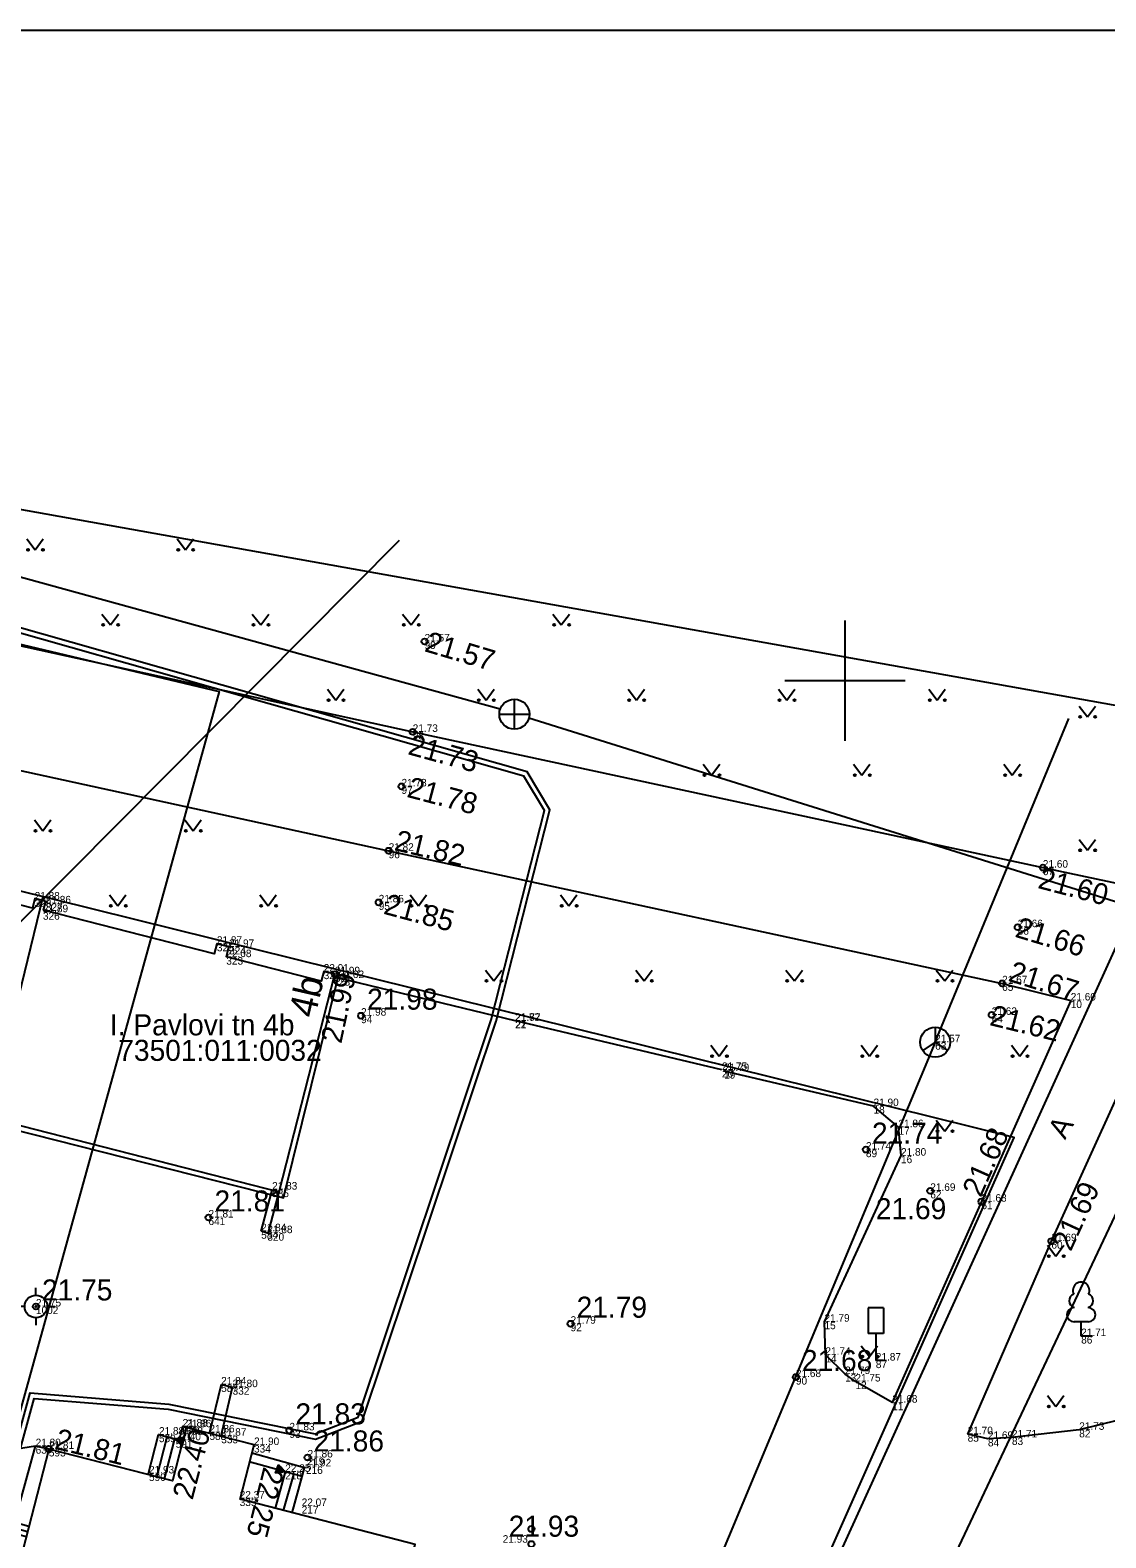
# Model space of a CAD drawing. Extents: x 714279 to 714471, y 6589851 to 6590083.
# Drawn here: x 714372.9 to 714408.7, y 6590021.5 to 6590071.6 of the extents above; entities that cross this region are included whole.
import ezdxf

# ---------------------------------------------------------------- set-up
doc = ezdxf.new("R2010")
doc.units = 0
for name, color, linetype in [('AED', 7, 'Continuous'), ('ALUSVORK', 7, 'Continuous'), ('HALJASTUS', 7, 'Continuous'), ('HOONE', 7, 'Continuous'), ('HOONEDET', 7, 'Continuous'), ('KKAEV', 7, 'Continuous'), ('KORGUS', 7, 'Continuous'), ('KTRASS', 7, 'Continuous'), ('LIIKLUS', 7, 'Continuous'), ('MOOTKORG', 7, 'Continuous'), ('MOOTMPUNKT', 7, 'Continuous'), ('MOOTPIIR', 7, 'Continuous'), ('MPKAABEL', 7, 'Continuous'), ('PIIR', 7, 'Continuous'), ('PUU', 7, 'Continuous'), ('SIKAEV', 7, 'Continuous'), ('SITRASS', 7, 'Continuous'), ('SKTRASS', 7, 'Continuous'), ('TEE', 7, 'Continuous'), ('VORK', 7, 'Continuous'), ('VORMISTUS', 7, 'Continuous'), ('VTRASS', 7, 'Continuous')]:
    doc.layers.add(name, color=color, linetype=linetype)

# ---------------------------------------------------------------- blocks, each defined once
blk = doc.blocks.new('RING02_1')
at = {"layer": 'KORGUS'}
blk.add_circle((0, 0), 0.2, dxfattribs=at)
blk = doc.blocks.new('RING02')
at = {"layer": 'KORGUS'}
blk.add_circle((0, 0), 0.2, dxfattribs=at)
blk = doc.blocks.new('SIKAEV')
at = {"layer": 'SIKAEV'}
for p, q in [((0, 0), (-0.83, -0.55)), ((0, 1), (0, 0)), ((0, 0), (0.83, -0.55))]:
    blk.add_line(p, q, dxfattribs=at)
blk.add_circle((0, 0), 1, dxfattribs=at)
blk = doc.blocks.new('RING02_2')
at = {"layer": 'KORGUS'}
blk.add_circle((0, 0), 0.2, dxfattribs=at)
blk = doc.blocks.new('LEHTP1')
at = {"layer": 'PUU'}
for p, q in [((0.48, 0.95), (-0.48, 0.95)), ((0, 0), (0, 0.95)), ((0.76, 0), (0, 0))]:
    blk.add_line(p, q, dxfattribs=at)
for centre, radius, start, end in [((0, 3.04), 0.554, 332.5799, 207.4201), ((-0.34, 2.35), 0.465, 109.0217, 253.1415), ((0.34, 2.35), 0.465, 286.8508, 70.9859), ((-0.47, 1.42), 0.475, 90.0016, 269.3953), ((0.47, 1.42), 0.475, 270.6047, 89.9984)]:
    blk.add_arc(centre, radius, start, end, dxfattribs=at)
blk = doc.blocks.new('LIIKLM')
at = {"layer": 'LIIKLUS'}
for p, q in [((-0.5, 3.5), (-0.5, 1.8)), ((0.5, 3.5), (-0.5, 3.5)), ((0.5, 3.5), (0.5, 1.8)), ((0.5, 1.8), (-0.5, 1.8)), ((0, 1.8), (0, 0)), ((0.5, 0), (0, 0))]:
    blk.add_line(p, q, dxfattribs=at)
blk = doc.blocks.new('RTKQRG')
at = {"layer": 'HOONEDET'}
for p, q in [((0, 0), (-0.49, 0.97)), ((0.49, 0.97), (-0.49, 0.97)), ((-0.48, 0.94), (0.21, 0.42)), ((-0.44, 0.97), (0.23, 0.46)), ((-0.42, 0.84), (0.19, 0.37)), ((-0.37, 0.74), (0.17, 0.33)), ((-0.35, 0.97), (0.26, 0.51)), ((-0.32, 0.63), (0.14, 0.28)), ((-0.27, 0.97), (0.28, 0.55)), ((-0.27, 0.53), (0.12, 0.24)), ((-0.22, 0.43), (0.1, 0.19)), ((-0.19, 0.97), (0.3, 0.6)), ((-0.17, 0.33), (0.07, 0.15)), ((-0.11, 0.97), (0.33, 0.64)), ((-0.11, 0.22), (0.05, 0.1)), ((-0.06, 0.12), (0.03, 0.05)), ((-0.02, 0.97), (0.35, 0.69)), ((-0.01, 0.02), (0, 0.01)), ((0, 0), (0.49, 0.97)), ((0.06, 0.97), (0.37, 0.73)), ((0.14, 0.97), (0.39, 0.78)), ((0.22, 0.97), (0.42, 0.83)), ((0.31, 0.97), (0.44, 0.87)), ((0.39, 0.97), (0.46, 0.92)), ((0.47, 0.97), (0.49, 0.96))]:
    blk.add_line(p, q, dxfattribs=at)
blk = doc.blocks.new('VQSA')
at = {"layer": 'HALJASTUS'}
for centre, radius in [((0, 2.3), 0.2), ((0, 1.3), 0.2), ((0, 0), 0.5), ((-2, -1.15), 0.2), ((-1.13, -0.65), 0.2), ((1.13, -0.65), 0.2), ((2, -1.15), 0.2)]:
    blk.add_circle(centre, radius, dxfattribs=at)
blk = doc.blocks.new('SPYMAR')
at = {"layer": 'ALUSVORK'}
for p, q in [((0, 0.75), (0, 1.25)), ((-0.75, 0), (-1.25, 0)), ((0.75, 0), (1.25, 0)), ((0, -0.75), (0, -1.25))]:
    blk.add_line(p, q, dxfattribs=at)
for radius in [0.75, 0.044]:
    blk.add_circle((0, 0), radius, dxfattribs=at)
blk = doc.blocks.new('KAKAEV')
at = {"layer": 'KKAEV'}
for p, q in [((-1, 0), (1, 0)), ((0, -1), (0, 1))]:
    blk.add_line(p, q, dxfattribs=at)
blk.add_circle((0, 0), 1, dxfattribs=at)
blk = doc.blocks.new('MURU_1')
at = {"layer": 'HALJASTUS'}
for p, q in [((-0.93, 1.21), (0, 0)), ((0, 0), (0.89, 1.21))]:
    blk.add_line(p, q, dxfattribs=at)
for centre in [(-0.8, 0), (0.86, 0)]:
    blk.add_circle(centre, 0.11, dxfattribs=at)

msp = doc.modelspace()

# ---------------------------------------------------------------- linework, layer by layer
at = {"layer": 'AED'}
for points in [[(714380.584, 6590031.676), (714380.945, 6590033.046)], [(714380.816, 6590031.599), (714381.181, 6590032.985)], [(714380.816, 6590031.599), (714380.584, 6590031.676)], [(714379.253, 6590026.577), (714378.863, 6590024.981), (714378.854, 6590024.945)], [(714379.249, 6590024.846), (714379.255, 6590024.871), (714379.255, 6590024.871), (714379.634, 6590026.487)], [(714379.253, 6590026.577), (714379.634, 6590026.487)], [(714381.948, 6590023.512), (714382.029, 6590023.801), (714380.27, 6590024.294)]]:
    msp.add_lwpolyline(points, dxfattribs=at)
at = {"layer": 'HOONE'}
for points in [[(714342.388, 6590042.923), (714381.181, 6590032.985), (714383.036, 6590040.226), (714382.666, 6590040.321), (714382.583, 6590039.999), (714379.427, 6590040.807), (714379.512, 6590041.139), (714379.11, 6590041.242), (714379.025, 6590040.91), (714373.344, 6590042.365), (714373.417, 6590042.65), (714373.056, 6590042.743), (714372.976, 6590042.431), (714367.537, 6590043.824)], [(714368.084, 6590003.497), (714362.833, 6589983.153), (714366.948, 6589982.091), (714366.479, 6589980.273), (714368.704, 6589979.699), (714369.168, 6589981.497), (714375.054, 6589979.978), (714385.707, 6590021.254), (714379.88, 6590022.758), (714380.346, 6590024.563), (714378.09, 6590025.145), (714377.63, 6590023.366), (714373.521, 6590024.426), (714369.05, 6590007.103), (714363.815, 6590008.455), (714364.534, 6590011.243), (714349.394, 6590015.151), (714346.235, 6590002.913), (714361.396, 6589999), (714362.901, 6590004.835), (714368.084, 6590003.497)], [(714378.09, 6590025.145), (714377.969, 6590025.177), (714377.855, 6590024.734)], [(714376.828, 6590023.573), (714377.174, 6590024.91), (714377.976, 6590024.703)], [(714377.116, 6590023.498), (714377.461, 6590024.836)], [(714377.372, 6590023.432), (714377.717, 6590024.769)], [(714381.61, 6590022.307), (714381.948, 6590023.512), (714380.189, 6590024.005)], [(714381.385, 6590023.67), (714381.047, 6590022.464)], [(714381.659, 6590023.586), (714381.321, 6590022.38)]]:
    msp.add_lwpolyline(points, dxfattribs=at)
at = {"layer": 'KORGUS'}
for centre in [(714383.036, 6590040.226), (714378.832, 6590032.133), (714373.093, 6590029.172), (714373.523, 6590024.432)]:
    msp.add_circle(centre, 0.1, dxfattribs=at)
at = {"layer": 'KTRASS'}
for points in [[(714388.535, 6590049.05), (714348.653, 6590060.023)], [(714409.141, 6590042.598), (714389.491, 6590048.747)], [(714399.928, 6590021.168), (714409.418, 6590042.018)]]:
    msp.add_lwpolyline(points, dxfattribs=at)
at = {"layer": 'MOOTPIIR'}
msp.add_lwpolyline([(714325.392, 6590064.148), (714418.405, 6590047.495), (714428.059, 6590039.059), (714392.952, 6589961.13), (714372.822, 6589966.903), (714302.696, 6589965.199), (714319.941, 6590042.637), (714325.392, 6590064.148)], dxfattribs=at)
at = {"layer": 'MPKAABEL'}
for points in [[(714372.812, 6590021.678), (714371.882, 6590021.934), (714373.032, 6590026.115), (714377.491, 6590025.755), (714382.392, 6590024.752), (714383.947, 6590025.358), (714388.404, 6590038.665), (714390.19, 6590045.703), (714389.431, 6590046.965), (714361.096, 6590055.017), (714347.738, 6590058.234), (714329.065, 6590059.739), (714322.338, 6590060.654), (714317.026, 6590061.747)], [(714372.768, 6590021.51), (714371.67, 6590021.813), (714372.903, 6590026.299), (714377.515, 6590025.926), (714382.377, 6590024.932), (714383.808, 6590025.49), (714388.238, 6590038.714), (714390.005, 6590045.675), (714389.318, 6590046.817), (714361.052, 6590054.85), (714347.71, 6590058.063), (714329.047, 6590059.566), (714322.309, 6590060.484), (714316.991, 6590061.578)]]:
    msp.add_lwpolyline(points, dxfattribs=at)
at = {"layer": 'PIIR'}
for points in [[(714313.433, 6589985.9), (714378.228, 6589973.152), (714405.629, 6590034.791), (714332.408, 6590052.951), (714332.595, 6590052.951)], [(714373.326, 6590042.802), (714371.485, 6590035.288), (714381.325, 6590032.79), (714383.187, 6590040.304)]]:
    msp.add_lwpolyline(points, dxfattribs=at)
at = {"layer": 'SITRASS'}
for points in [[(714320.359, 6590061.207), (714337.402, 6590059.587), (714379.185, 6590049.636), (714371.595, 6590022.212), (714372.86, 6590021.865)], [(714403.003, 6590037.966), (714407.447, 6590048.741)], [(714403.003, 6590037.966), (714373.288, 6589966.766)]]:
    msp.add_lwpolyline(points, dxfattribs=at)
at = {"layer": 'SKTRASS'}
msp.add_lwpolyline([(714355.498, 6590024.768), (714385.19, 6590054.667)], dxfattribs=at)
at = {"layer": 'TEE'}
for points in [[(714333.617, 6590059.437), (714358.94, 6590054.148), (714385.625, 6590048.292), (714406.584, 6590043.775), (714409.241, 6590043.211)], [(714332.593, 6590055.546), (714358.028, 6590050.175), (714384.824, 6590044.337), (714405.232, 6590039.925)], [(714389.03, 6590038.681), (714383.172, 6590040.1)], [(714405.232, 6590039.925), (714405.232, 6590039.925), (714407.513, 6590039.354)], [(714407.513, 6590039.354), (714401.577, 6590025.972), (714400.35, 6590026.676), (714400.006, 6590026.924), (714399.352, 6590027.564), (714399.321, 6590028.666), (714401.867, 6590034.191), (714401.782, 6590035.138), (714400.953, 6590035.84), (714395.983, 6590037.004)], [(714395.911, 6590037.044), (714389.038, 6590038.673)], [(714404.084, 6590024.922), (714404.084, 6590024.922), (714406.869, 6590031.347), (714410.261, 6590038.815), (714411.152, 6590038.233), (714411.748, 6590037.728), (714412.277, 6590037.152), (714412.789, 6590036.481), (714413.097, 6590035.78), (714413.331, 6590034.96), (714413.433, 6590034.186), (714413.432, 6590033.354), (714413.365, 6590032.606), (714413.139, 6590031.771), (714412.887, 6590030.992), (714410.681, 6590026.115), (714409.734, 6590025.55), (714407.795, 6590025.068), (714405.557, 6590024.814), (714404.758, 6590024.766), (714404.084, 6590024.922)], [(714368.928, 6590009.453), (714373.082, 6590024.523), (714370.895, 6590024.179), (714369.109, 6590016.749), (714367.271, 6590009.843)], [(714373.521, 6590024.426), (714373.082, 6590024.523)]]:
    msp.add_lwpolyline(points, dxfattribs=at)
at = {"layer": 'VORK'}
for p, q in [((714400, 6590052), (714400, 6590048)), ((714398, 6590050), (714402, 6590050))]:
    msp.add_line(p, q, dxfattribs=at)
at = {"layer": 'VORMISTUS'}
msp.add_lwpolyline([(714471.122, 6589929.143), (714278.622, 6589929.143), (714278.622, 6590071.643), (714471.122, 6590071.643), (714471.122, 6589929.143)], dxfattribs=at)
at = {"layer": 'VTRASS'}
msp.add_lwpolyline([(714378.183, 6589965.384), (714401.816, 6590016.993), (714414.734, 6590044.36), (714416.367, 6590047.881)], dxfattribs=at)

# ---------------------------------------------------------------- block references
at = {"layer": 'ALUSVORK', "xscale": 0.5, "yscale": 0.5}
msp.add_blockref('SPYMAR', (714373.093, 6590029.172), dxfattribs=at)
at = {"layer": 'HALJASTUS'}
for name, p, xscale, yscale in [('MURU_1', (714373.068, 6590054.352), 0.3, 0.3), ('MURU_1', (714378.068, 6590054.352), 0.3, 0.3), ('MURU_1', (714375.568, 6590051.852), 0.3, 0.3), ('MURU_1', (714380.568, 6590051.852), 0.3, 0.3), ('MURU_1', (714385.568, 6590051.852), 0.3, 0.3), ('MURU_1', (714390.568, 6590051.852), 0.3, 0.3), ('MURU_1', (714383.068, 6590049.352), 0.3, 0.3), ('MURU_1', (714388.068, 6590049.352), 0.3, 0.3), ('MURU_1', (714393.068, 6590049.352), 0.3, 0.3), ('MURU_1', (714398.068, 6590049.352), 0.3, 0.3), ('MURU_1', (714403.068, 6590049.352), 0.3, 0.3), ('MURU_1', (714408.068, 6590048.789), 0.3, 0.3), ('MURU_1', (714395.568, 6590046.852), 0.3, 0.3), ('MURU_1', (714400.568, 6590046.852), 0.3, 0.3), ('MURU_1', (714405.568, 6590046.852), 0.3, 0.3), ('MURU_1', (714373.32, 6590045.004), 0.3, 0.3), ('MURU_1', (714378.32, 6590045.004), 0.3, 0.3), ('MURU_1', (714408.068, 6590044.352), 0.3, 0.3), ('MURU_1', (714375.82, 6590042.504), 0.3, 0.3), ('MURU_1', (714380.82, 6590042.504), 0.3, 0.3), ('MURU_1', (714385.82, 6590042.504), 0.3, 0.3), ('MURU_1', (714390.82, 6590042.504), 0.3, 0.3), ('MURU_1', (714388.32, 6590040.004), 0.3, 0.3), ('MURU_1', (714393.32, 6590040.004), 0.3, 0.3), ('MURU_1', (714398.32, 6590040.004), 0.3, 0.3), ('MURU_1', (714403.32, 6590040.004), 0.3, 0.3), ('MURU_1', (714395.82, 6590037.504), 0.3, 0.3), ('MURU_1', (714400.82, 6590037.504), 0.3, 0.3), ('MURU_1', (714405.82, 6590037.504), 0.3, 0.3), ('MURU_1', (714403.32, 6590035.004), 0.3, 0.3), ('MURU_1', (714407.02, 6590030.846), 0.3, 0.3), ('MURU_1', (714400.82, 6590027.504), 0.3, 0.3), ('MURU_1', (714407.02, 6590025.846), 0.3, 0.3), ('VQSA', (714389.571, 6590020.618), 0.5, 0.5)]:
    msp.add_blockref(name, p, dxfattribs=dict(at, xscale=xscale, yscale=yscale))
at = {"layer": 'HOONEDET'}
for p, xscale, yscale, rotation in [((714377.717, 6590024.769), 0.29999999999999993, 0.3, -106.23872594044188), ((714381.385, 6590023.67), 0.3, -0.3, -109.050816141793)]:
    msp.add_blockref('RTKQRG', p, dxfattribs=dict(at, xscale=xscale, yscale=yscale, rotation=rotation))
at = {"layer": 'KKAEV', "xscale": 0.5, "yscale": 0.5}
msp.add_blockref('KAKAEV', (714389.006, 6590048.881), dxfattribs=at)
at = {"layer": 'KORGUS', "xscale": 0.5, "yscale": 0.5}
for name, p in [('RING02', (714386.02, 6590051.301)), ('RING02_2', (714385.625, 6590048.292)), ('RING02_1', (714385.251, 6590046.478)), ('RING02_2', (714384.824, 6590044.337)), ('RING02_2', (714406.584, 6590043.775)), ('RING02', (714384.494, 6590042.619)), ('RING02_1', (714405.748, 6590041.793)), ('RING02_2', (714405.232, 6590039.925)), ('RING02', (714383.908, 6590038.849)), ('RING02', (714404.885, 6590038.876)), ('RING02', (714400.7, 6590034.391)), ('RING02', (714402.841, 6590033.02)), ('RING02_1', (714404.542, 6590032.66)), ('RING02_1', (714406.869, 6590031.347)), ('RING02', (714390.876, 6590028.598)), ('RING02', (714398.371, 6590026.823)), ('RING02', (714381.523, 6590025.049)), ('RING02_1', (714382.128, 6590024.147))]:
    msp.add_blockref(name, p, dxfattribs=at)
at = {"layer": 'LIIKLUS', "xscale": 0.5, "yscale": 0.5}
msp.add_blockref('LIIKLM', (714401.029, 6590027.372), dxfattribs=at)
at = {"layer": 'PUU', "xscale": 0.5, "yscale": 0.5}
msp.add_blockref('LEHTP1', (714407.859, 6590028.187), dxfattribs=at)
at = {"layer": 'SIKAEV', "xscale": 0.5, "yscale": 0.5}
msp.add_blockref('SIKAEV', (714403.003, 6590037.966), dxfattribs=at)

# ---------------------------------------------------------------- texts
at = {"layer": 'HOONE'}
msp.add_text('4b', height=0.9, rotation=77.1111, dxfattribs=at).set_placement((714382.373, 6590038.744))
at = {"layer": 'HOONEDET'}
for s, rotation, p in [('22.40', 75.1609, (714378.3, 6590022.711)), ('22.25', 255.7051, (714380.668, 6590023.863))]:
    msp.add_text(s, height=0.7, rotation=rotation, dxfattribs=at).set_placement(p)
at = {"layer": 'KORGUS'}
for s, rotation, p in [('21.57', 343.3438, (714385.985, 6590050.982)), ('21.73', 344.5987, (714385.433, 6590047.554)), ('21.78', 345.1188, (714385.4, 6590046.134)), ('21.82', 346.6705, (714384.983, 6590044.361)), ('21.60', 345.2509, (714406.386, 6590043.102)), ('21.85', 344.948, (714384.623, 6590042.245)), ('21.66', 343.0663, (714405.625, 6590041.48)), ('21.67', 342.5464, (714405.401, 6590040.014)), ('21.99', 77.9478, (714383.248, 6590037.896)), ('21.62', 346.1662, (714404.785, 6590038.541)), ('21.68', 66.1218, (714404.52, 6590032.776)), ('21.69', 65.2812, (714407.514, 6590030.978)), ('21.81', 346.1293, (714373.683, 6590024.445))]:
    msp.add_text(s, height=0.7, rotation=rotation, dxfattribs=at).set_placement(p)
for s, p in [('21.98', (714384.108, 6590039.049)), ('21.74', (714400.9, 6590034.591)), ('21.81', (714379.032, 6590032.333)), ('21.69', (714401.031, 6590032.077)), ('21.75', (714373.293, 6590029.372)), ('21.79', (714391.076, 6590028.798)), ('21.68', (714398.571, 6590027.023)), ('21.83', (714381.723, 6590025.249)), ('21.86', (714382.328, 6590024.347)), ('21.93', (714388.818, 6590021.511))]:
    msp.add_text(s, height=0.7, dxfattribs=at).set_placement(p)
at = {"layer": 'MOOTKORG'}
for s, p in [('21.57', (714386.02, 6590051.301)), ('21.73', (714385.625, 6590048.292)), ('21.78', (714385.251, 6590046.478)), ('21.82', (714384.824, 6590044.337)), ('21.60', (714406.584, 6590043.775)), ('21.88', (714373.049, 6590042.714)), ('21.89', (714373.325, 6590042.291)), ('21.86', (714373.42, 6590042.586)), ('21.85', (714384.494, 6590042.619)), ('21.66', (714405.748, 6590041.793)), ('21.87', (714379.111, 6590041.241)), ('22.08', (714379.424, 6590040.797)), ('21.97', (714379.516, 6590041.137)), ('22.01', (714382.664, 6590040.315)), ('21.99', (714383.036, 6590040.226)), ('22.02', (714383.172, 6590040.1)), ('21.67', (714405.232, 6590039.925)), ('21.60', (714407.513, 6590039.354)), ('21.98', (714383.908, 6590038.849)), ('21.62', (714404.885, 6590038.876)), ('21.82', (714389.03, 6590038.681)), ('21.77', (714389.038, 6590038.673)), ('21.57', (714403.003, 6590037.966)), ('21.75', (714395.911, 6590037.044)), ('21.79', (714395.983, 6590037.004)), ('21.90', (714400.953, 6590035.84)), ('21.86', (714401.782, 6590035.138)), ('21.74', (714400.7, 6590034.391)), ('21.80', (714401.867, 6590034.191)), ('21.83', (714380.949, 6590033.062)), ('21.69', (714402.841, 6590033.02)), ('21.68', (714404.542, 6590032.66)), ('21.81', (714378.832, 6590032.133)), ('21.84', (714380.584, 6590031.676)), ('21.88', (714380.79, 6590031.612)), ('21.69', (714406.869, 6590031.347)), ('21.75', (714373.093, 6590029.172)), ('21.79', (714390.876, 6590028.598)), ('21.79', (714399.321, 6590028.666)), ('21.71', (714407.859, 6590028.187)), ('21.74', (714399.352, 6590027.564)), ('21.87', (714401.029, 6590027.372)), ('21.68', (714398.371, 6590026.823)), ('21.79', (714400.006, 6590026.924)), ('21.84', (714379.253, 6590026.577)), ('21.80', (714379.634, 6590026.487)), ('21.75', (714400.35, 6590026.676)), ('21.68', (714401.577, 6590025.972)), ('21.88', (714377.184, 6590024.907)), ('21.88', (714377.969, 6590025.175)), ('21.86', (714378.092, 6590025.154)), ('21.86', (714378.863, 6590024.981)), ('21.87', (714379.255, 6590024.871)), ('21.83', (714381.523, 6590025.049)), ('21.70', (714404.084, 6590024.922)), ('21.69', (714404.758, 6590024.766)), ('21.71', (714405.557, 6590024.814)), ('21.73', (714407.795, 6590025.068)), ('21.80', (714373.082, 6590024.523)), ('21.81', (714373.523, 6590024.432)), ('22.40', (714377.742, 6590024.721)), ('21.90', (714380.347, 6590024.562)), ('21.92', (714382.076, 6590023.852)), ('21.86', (714382.128, 6590024.147)), ('21.93', (714376.853, 6590023.616)), ('22.25', (714381.385, 6590023.67)), ('22.37', (714379.87, 6590022.782)), ('22.07', (714381.931, 6590022.533)), ('21.93', (714388.618, 6590021.311))]:
    msp.add_text(s, height=0.25, dxfattribs=at).set_placement(p)
at = {"layer": 'MOOTMPUNKT'}
for s, p in [('99', (714386.02, 6590051.051)), ('98', (714385.625, 6590048.042)), ('97', (714385.251, 6590046.228)), ('96', (714384.824, 6590044.087)), ('67', (714406.584, 6590043.525)), ('328', (714373.049, 6590042.464)), ('327', (714373.42, 6590042.336)), ('95', (714384.494, 6590042.369)), ('326', (714373.325, 6590042.041)), ('66', (714405.748, 6590041.543)), ('325', (714379.111, 6590040.991)), ('324', (714379.516, 6590040.887)), ('323', (714379.424, 6590040.547)), ('322', (714382.664, 6590040.065)), ('321', (714383.036, 6590039.976)), ('23', (714383.172, 6590039.85)), ('65', (714405.232, 6590039.675)), ('10', (714407.513, 6590039.104)), ('94', (714383.908, 6590038.599)), ('22', (714389.03, 6590038.431)), ('21', (714389.038, 6590038.423)), ('64', (714404.885, 6590038.626)), ('63', (714403.003, 6590037.716)), ('20', (714395.911, 6590036.794)), ('19', (714395.983, 6590036.754)), ('18', (714400.953, 6590035.59)), ('17', (714401.782, 6590034.888)), ('89', (714400.7, 6590034.141)), ('16', (714401.867, 6590033.941)), ('585', (714380.949, 6590032.812)), ('62', (714402.841, 6590032.77)), ('61', (714404.542, 6590032.41)), ('641', (714378.832, 6590031.883)), ('584', (714380.584, 6590031.426)), ('320', (714380.79, 6590031.362)), ('60', (714406.869, 6590031.097)), ('1002', (714373.093, 6590028.922)), ('92', (714390.876, 6590028.348)), ('15', (714399.321, 6590028.416)), ('86', (714407.859, 6590027.937)), ('14', (714399.352, 6590027.314)), ('87', (714401.029, 6590027.122)), ('587', (714379.253, 6590026.327)), ('332', (714379.634, 6590026.237)), ('90', (714398.371, 6590026.573)), ('13', (714400.006, 6590026.674)), ('12', (714400.35, 6590026.426)), ('11', (714401.577, 6590025.722)), ('640', (714377.969, 6590024.925)), ('592', (714378.092, 6590024.904)), ('588', (714378.863, 6590024.731)), ('93', (714381.523, 6590024.799)), ('82', (714407.795, 6590024.818)), ('637', (714373.082, 6590024.273)), ('589', (714377.184, 6590024.657)), ('591', (714377.742, 6590024.471)), ('333', (714379.255, 6590024.621)), ('334', (714380.347, 6590024.312)), ('85', (714404.084, 6590024.672)), ('84', (714404.758, 6590024.516)), ('83', (714405.557, 6590024.564)), ('593', (714373.523, 6590024.182)), ('219', (714382.128, 6590023.897)), ('590', (714376.853, 6590023.366)), ('218', (714381.385, 6590023.42)), ('216', (714382.076, 6590023.602)), ('335', (714379.87, 6590022.532)), ('217', (714381.931, 6590022.283))]:
    msp.add_text(s, height=0.25, dxfattribs=at).set_placement(p)
at = {"layer": 'PIIR'}
for s, p in [('I. Pavlovi tn 4b', (714375.552, 6590038.194)), ('73501:011:0032', (714375.831, 6590037.345))]:
    msp.add_text(s, height=0.7, dxfattribs=at).set_placement(p)
at = {"layer": 'TEE'}
msp.add_text('A', height=0.7, rotation=60.3651, dxfattribs=at).set_placement((714407.324, 6590034.701))

doc.saveas('drawing.dxf')
